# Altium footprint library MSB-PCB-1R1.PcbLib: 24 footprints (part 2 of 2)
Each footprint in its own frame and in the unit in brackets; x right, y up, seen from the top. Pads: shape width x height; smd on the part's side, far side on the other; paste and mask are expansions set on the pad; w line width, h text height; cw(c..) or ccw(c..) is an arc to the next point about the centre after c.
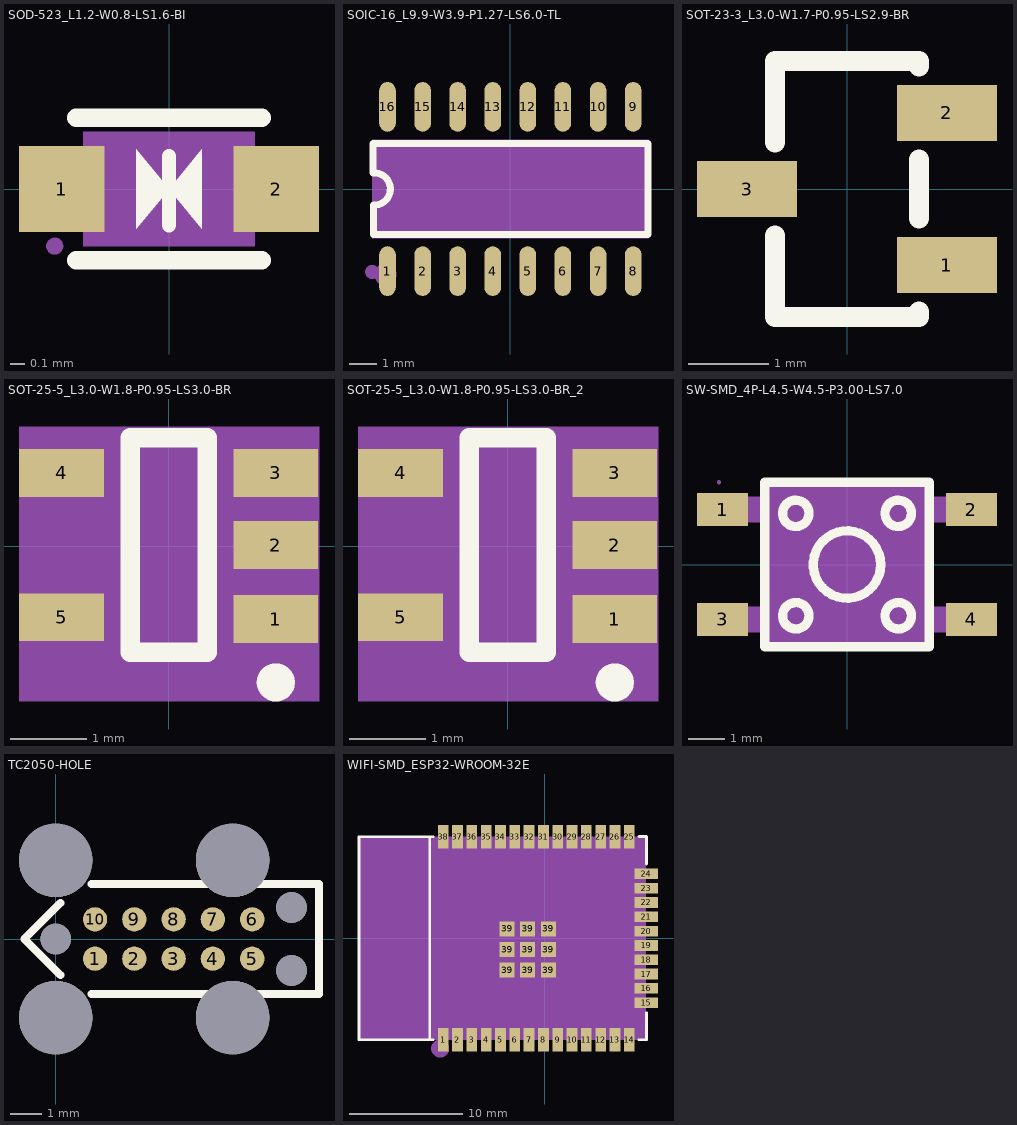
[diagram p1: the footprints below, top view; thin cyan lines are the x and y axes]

## SOD-523_L1.2-W0.8-LS1.6-BI [mm]
pads (2):
  rect 0.6x0.6 smd: 1(-0.75,0) 2(0.75,0)
Top Overlay:
  region: 0,0 0.229,0.279 0.229,-0.279
  region: 0,0 -0.229,-0.279 -0.229,0.279
  lines w0.1: 0,-0.254 0,0.229
  lines w0.13: -0.65,-0.5 0.65,-0.5 ; -0.65,0.5 0.65,0.5
Mechanical 4:
  region: -0.6,-0.4 -0.6,0.4 0.6,0.4 0.6,-0.4
Mechanical 5:
  region: 0.8,-0.152 0.463,-0.152 0.463,0.148 0.8,0.148
  region: -0.8,0.15 -0.463,0.15 -0.463,-0.15 -0.8,-0.15
Mechanical 6:
  circle w0.06: c-0.8,-0.4 r0.03
Mechanical 15:
  region: -0.229,0.279 -0.229,-0.279 0,0
  region: 0.229,0.279 0.229,-0.279 0,0

## SOIC-16_L9.9-W3.9-P1.27-LS6.0-TL [mm]
pads (16):
  oval 0.6x1.8 smd: 1(-4.445,-2.972) 2(-3.175,-2.972) 3(-1.905,-2.972) 4(-0.635,-2.972) 5(0.635,-2.972) 6(1.905,-2.972) 7(3.175,-2.972) 8(4.445,-2.972) 9(4.445,2.972) 10(3.175,2.972) 11(1.905,2.972) 12(0.635,2.972) 13(-0.635,2.972) 14(-1.905,2.972) 15(-3.175,2.972) 16(-4.445,2.972)
Top Overlay:
  lines w0.254: -4.976,0.584 -4.976,1.651 4.976,1.651 4.976,-1.651 2.703,-1.651 -2.655,-1.651 -4.953,-1.651 -4.953,-0.584 ccw(c-4.928,0) -4.95,0.584
Mechanical 4:
  region: -5,1.778 5,1.778 5,-1.778 -5,-1.778
Mechanical 6:
  circle w0.254: c-5,-3 r0.127
Mechanical 15:
  circle w0.4: c-4.521,-3.099 r0.2

## SOT-23-3_L3.0-W1.7-P0.95-LS2.9-BR [mm]
pads (3):
  rect 1.25x0.7 smd: 1(1.25,-0.95) 2(1.25,0.95) 3(-1.25,0)
Top Overlay:
  lines w0.254: -0.9,-0.581 -0.9,-1.6 0.9,-1.6 0.9,-1.531 ; -0.9,0.581 -0.9,1.6 0.9,1.6 0.9,1.531 ; 0.9,-0.369 0.9,0.369

## SOT-25-5_L3.0-W1.8-P0.95-LS3.0-BR [mil]
pads (5):
  rect 43.5x24.5 smd: 1(55,-37.5) 2(55,0.5) 3(55,37.5) 4(-55,37.5) 5(-55,-36.5)
Top Overlay:
  lines w9.8: 59.9,-70.05 cw(c55,-70) 59.9,-69.95
  lines w10: -19.7,-54.6 -19.7,55.6 19.7,55.6 19.7,-54.6 -19.7,-54.6
Mechanical 4:
  region: -76.83,61.33 77.17,61.33 77.17,-79.8 -76.83,-79.8
Mechanical 5:
  region: -76.75,49.75 -33.25,49.75 -33.25,25.25 -76.75,25.25
  region: -76.75,-24.25 -33.25,-24.25 -33.25,-48.75 -76.75,-48.75
  region: 33.25,-25.25 76.75,-25.25 76.75,-49.75 33.25,-49.75
  region: 33.25,12.75 76.75,12.75 76.75,-11.75 33.25,-11.75
  region: 33.25,49.75 76.75,49.75 76.75,25.25 33.25,25.25

## SOT-25-5_L3.0-W1.8-P0.95-LS3.0-BR_2 [mil]
pads (5):
  rect 43.5x24.5 smd: 1(55,-37.5) 2(55,0.5) 3(55,37.5) 4(-55,37.5) 5(-55,-36.5)
Top Overlay:
  lines w9.8: 59.9,-70.05 cw(c55,-70) 59.9,-69.95
  lines w10: -19.7,-54.6 19.7,-54.6 19.7,55.6 -19.7,55.6 -19.7,-54.6
Mechanical 4:
  region: -76.83,61.33 77.17,61.33 77.17,-79.8 -76.83,-79.8
Mechanical 5:
  region: 33.25,49.75 76.75,49.75 76.75,25.25 33.25,25.25
  region: 33.25,12.75 76.75,12.75 76.75,-11.75 33.25,-11.75
  region: 33.25,-25.25 76.75,-25.25 76.75,-49.75 33.25,-49.75
  region: -76.75,-24.25 -33.25,-24.25 -33.25,-48.75 -76.75,-48.75
  region: -76.75,49.75 -33.25,49.75 -33.25,25.25 -76.75,25.25

## SW-SMD_4P-L4.5-W4.5-P3.00-LS7.0 [mm]
pads (4):
  rect 1.4x0.9 smd: 1(-3.4,1.5) 2(3.4,1.5) 3(-3.4,-1.5) 4(3.4,-1.5)
Top Overlay:
  circle w0.254: c0,0 r0.922
  circle w0.254: c1.4,1.4 r0.361
  circle w0.254: c-1.4,1.4 r0.361
  circle w0.254: c-1.4,-1.4 r0.361
  circle w0.254: c1.4,-1.4 r0.361
  lines w0.254: -2.25,-2.25 2.25,-2.25 2.25,2.25 -2.25,2.25 -2.25,-2.25
Mechanical 4:
  region: -2.25,-2.25 -2.25,2.25 2.25,2.25 2.25,-2.25
Mechanical 5:
  pour cut-out: 2.24,-1.85 2.24,-1.15 3.01,-1.15 3.01,-1.85
  region: 3,-1.85 3,-1.15 3.5,-1.15 3.5,-1.85
  pour cut-out: -3.01,-1.85 -3.01,-1.15 -2.24,-1.15 -2.24,-1.85
  region: -3.5,-1.85 -3.5,-1.15 -3,-1.15 -3,-1.85
  pour cut-out: 2.24,1.15 2.24,1.85 3.01,1.85 3.01,1.15
  region: 3,1.15 3,1.85 3.5,1.85 3.5,1.15
  pour cut-out: -3.01,1.15 -3.01,1.85 -2.24,1.85 -2.24,1.15
  region: -3.5,1.15 -3.5,1.85 -3,1.85 -3,1.15
Mechanical 6:
  circle w0.06: c-3.5,2.25 r0.03

## TC2050-HOLE [mm]
pads (17):
  round 0.787 smd: 1(1.27,-0.635) 2(2.54,-0.635) 3(3.81,-0.635) 4(5.08,-0.635) 5(6.35,-0.635) 6(6.35,0.635) 7(5.08,0.635) 8(3.81,0.635) 9(2.54,0.635) 10(1.27,0.635)
  round 2.375 hole 2.375 unplated: ""(0,-2.54) ""(0,2.54) ""(5.715,-2.54) ""(5.715,2.54)
  round 0.991 hole 0.991 unplated: ""(0,0) ""(7.62,-1.016) ""(7.62,1.016)
Top Overlay:
  lines w0.254: 0.153,-1.169 -1.016,0 ; 1.151,-1.778 2.024,-1.778 4.473,-1.778 ; 1.151,1.778 2.024,1.778 ; 1.867,1.778 4.326,1.778 5.842,1.778 8.509,1.778 8.509,-1.778 4.326,-1.778 ; -1.016,0 0.153,1.169 -1.016,0

## WIFI-SMD_ESP32-WROOM-32E [mm]
pads (47):
  rect 0.95x2.1 smd: 1(-9.002,-9) 2(-7.732,-9) 3(-6.462,-9) 4(-5.192,-9) 5(-3.922,-9) 6(-2.652,-9) 7(-1.382,-9) 8(-0.112,-9) 9(1.158,-9) 10(2.428,-9) 11(3.698,-9) 12(4.968,-9) 13(6.238,-9) 14(7.508,-9) 25(7.507,9) 26(6.237,9) 27(4.967,9) 28(3.697,9) 29(2.427,9) 30(1.157,9) 31(-0.113,9) 32(-1.383,9) 33(-2.653,9) 34(-3.923,9) 35(-5.193,9) 36(-6.463,9) 37(-7.733,9) 38(-9.003,9)
  rect 2.1x0.95 smd: 15(9.002,-5.715) 16(9.002,-4.445) 17(9.002,-3.175) 18(9.002,-1.905) 19(9.002,-0.635) 20(9.002,0.635) 21(9.002,1.905) 22(9.002,3.175) 23(9.002,4.445) 24(9.002,5.715)
  rect 1.33x1.33 smd: 39(-3.337,-2.835) 39(-3.337,-1) 39(-3.337,0.835) 39(-1.502,-2.835) 39(-1.502,-1) 39(-1.502,0.835) 39(0.333,-2.835) 39(0.333,-1) 39(0.333,0.835)
Top Overlay:
  lines w0.254: -10.192,-9 -10.192,9 ; -9.906,-9 -16.476,-9 -16.476,9 -9.906,9 ; 8.382,-9 9.024,-9 9.024,-6.604 ; 8.382,9.017 9.024,9.017 9.024,6.604
Mechanical 4:
  region: -16.528,-9 -16.528,9 8.972,9 8.972,-9
Mechanical 5:
  drawing of 47 lines, arcs and shapes, not listed
Mechanical 6:
  circle w0.06: c-16.528,-9 r0.03
Mechanical 15:
  circle w0.8: c-9.264,-9.779 r0.4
